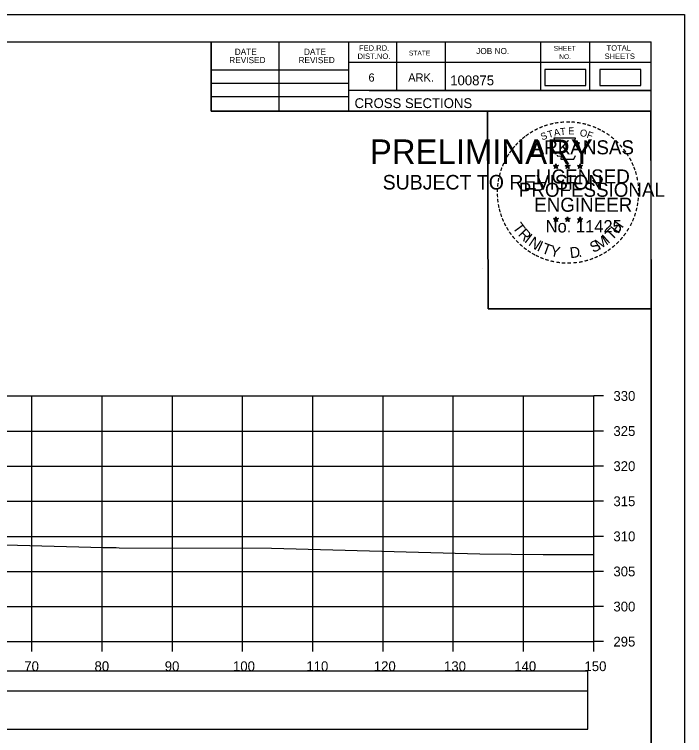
# Model space of a CAD drawing. Extents: x 1368122 to 1710785, y 373130 to 557566.
# Drawn here: x 1370089.7 to 1370185.2, y 375587.6 to 375690.4 of the extents above; entities that cross this region are included whole.
import ezdxf

# ---------------------------------------------------------------- set-up
doc = ezdxf.new("R2010")
doc.units = 0
for name, color, linetype in [('R_Axis', 7, 'Continuous'), ('R_Axis Annot', 7, 'Continuous'), ('R_Border', 7, 'Continuous'), ('R_Border PE', 7, 'Continuous'), ('R_Border Prem', 7, 'Continuous'), ('R_Drive', 7, 'Continuous'), ('R_Exist Surface', 7, 'Continuous'), ('R_Grid', 7, 'Continuous'), ('R_No Plot', 7, 'Continuous')]:
    doc.layers.add(name, color=color, linetype=linetype)

msp = doc.modelspace()

# ---------------------------------------------------------------- linework, layer by layer
for points in [[(1369873.09, 375594.02), (1370171.39, 375594.02), (1370171.39, 375596.84), (1369873.09, 375596.84)], [(1369873.09, 375588.55), (1370171.39, 375588.55), (1370171.39, 375593.96), (1369873.09, 375593.96)]]:
    msp.add_lwpolyline(points, close=True)
at = {"layer": 'R_Axis'}
for p, q in [((1370172.24, 375601.03), (1370172.24, 375636.03)), ((1370173.64, 375636.03), (1370172.24, 375636.03)), ((1370173.64, 375631.03), (1370172.24, 375631.03)), ((1370173.64, 375626.03), (1370172.24, 375626.03)), ((1370173.64, 375621.03), (1370172.24, 375621.03)), ((1370173.64, 375616.03), (1370172.24, 375616.03)), ((1370173.64, 375611.03), (1370172.24, 375611.03)), ((1370173.64, 375606.03), (1370172.24, 375606.03)), ((1369872.24, 375601.03), (1370172.24, 375601.03)), ((1370092.24, 375599.63), (1370092.24, 375601.03)), ((1370102.24, 375599.63), (1370102.24, 375601.03)), ((1370112.24, 375599.63), (1370112.24, 375601.03)), ((1370122.24, 375599.63), (1370122.24, 375601.03)), ((1370132.24, 375599.63), (1370132.24, 375601.03)), ((1370142.24, 375599.63), (1370142.24, 375601.03)), ((1370152.24, 375599.63), (1370152.24, 375601.03)), ((1370162.24, 375599.63), (1370162.24, 375601.03)), ((1370172.24, 375599.63), (1370172.24, 375601.03)), ((1370173.64, 375601.03), (1370172.24, 375601.03))]:
    msp.add_line(p, q, dxfattribs=at)
at = {"layer": 'R_Border'}
for p, q in [((1369864.24, 375686.49), (1370180.42, 375686.49)), ((1370117.78, 375676.61), (1370117.78, 375686.49)), ((1370127.46, 375676.61), (1370127.46, 375686.49)), ((1370137.32, 375686.49), (1370137.32, 375676.61)), ((1370144.16, 375686.49), (1370144.16, 375679.55)), ((1370151.1, 375686.49), (1370151.1, 375679.55)), ((1370164.68, 375686.49), (1370164.68, 375679.55)), ((1370171.62, 375686.49), (1370171.62, 375679.55)), ((1370180.42, 375481.03), (1370180.42, 375686.49)), ((1370180.42, 375683.55), (1370137.32, 375683.55)), ((1370180.42, 375683.57), (1370180.42, 375683.57)), ((1370117.78, 375682.47), (1370137.32, 375682.47)), ((1370117.78, 375680.61), (1370137.32, 375680.61)), ((1370180.42, 375679.55), (1370137.32, 375679.55)), ((1370140.28, 375679.55), (1370180.42, 375679.55)), ((1370117.78, 375678.67), (1370137.32, 375678.67)), ((1370180.42, 375676.61), (1370117.78, 375676.61))]:
    msp.add_line(p, q, dxfattribs=at)
at = {"layer": 'R_Border PE'}
for p, q in [((1370166.51, 375668.86), (1370166.85, 375668.75)), ((1370166.51, 375668.86), (1370166.76, 375668.82)), ((1370166.51, 375668.86), (1370166.74, 375668.74)), ((1370166.64, 375668.45), (1370166.85, 375668.75)), ((1370166.64, 375668.45), (1370166.76, 375668.7)), ((1370166.64, 375668.45), (1370166.85, 375668.67)), ((1370166.85, 375669.12), (1370166.81, 375668.86)), ((1370166.85, 375668.75), (1370166.85, 375669.12)), ((1370166.85, 375669.12), (1370166.9, 375668.87)), ((1370167.2, 375668.86), (1370166.85, 375668.75)), ((1370167.07, 375668.45), (1370166.85, 375668.75)), ((1370167.07, 375668.45), (1370166.85, 375668.67)), ((1370167.2, 375668.86), (1370166.92, 375668.81)), ((1370167.07, 375668.45), (1370166.93, 375668.75)), ((1370167.2, 375668.86), (1370167, 375668.76)), ((1370168.18, 375668.86), (1370168.52, 375668.75)), ((1370168.18, 375668.86), (1370168.43, 375668.82)), ((1370168.18, 375668.86), (1370168.41, 375668.74)), ((1370168.31, 375668.45), (1370168.52, 375668.75)), ((1370168.31, 375668.45), (1370168.43, 375668.7)), ((1370168.31, 375668.45), (1370168.52, 375668.67)), ((1370168.52, 375669.12), (1370168.48, 375668.86)), ((1370168.52, 375668.75), (1370168.52, 375669.12)), ((1370168.52, 375669.12), (1370168.57, 375668.87)), ((1370168.87, 375668.86), (1370168.52, 375668.75)), ((1370168.74, 375668.45), (1370168.52, 375668.75)), ((1370168.74, 375668.45), (1370168.52, 375668.67)), ((1370168.87, 375668.86), (1370168.59, 375668.81)), ((1370168.74, 375668.45), (1370168.6, 375668.75)), ((1370168.87, 375668.86), (1370168.67, 375668.76)), ((1370169.94, 375668.85), (1370170.29, 375668.74)), ((1370169.94, 375668.85), (1370170.19, 375668.81)), ((1370169.94, 375668.85), (1370170.18, 375668.73)), ((1370170.07, 375668.44), (1370170.29, 375668.74)), ((1370170.07, 375668.44), (1370170.2, 375668.69)), ((1370170.07, 375668.44), (1370170.29, 375668.66)), ((1370170.29, 375669.1), (1370170.25, 375668.85)), ((1370170.29, 375668.74), (1370170.29, 375669.1)), ((1370170.29, 375669.1), (1370170.34, 375668.85)), ((1370170.64, 375668.85), (1370170.29, 375668.74)), ((1370170.5, 375668.44), (1370170.29, 375668.74)), ((1370170.5, 375668.44), (1370170.29, 375668.66)), ((1370170.64, 375668.85), (1370170.35, 375668.8)), ((1370170.5, 375668.44), (1370170.36, 375668.73)), ((1370170.64, 375668.85), (1370170.43, 375668.75)), ((1370166.85, 375661.54), (1370166.81, 375661.29)), ((1370166.85, 375661.18), (1370166.85, 375661.54)), ((1370166.85, 375661.54), (1370166.9, 375661.29)), ((1370168.52, 375661.54), (1370168.48, 375661.29)), ((1370168.52, 375661.18), (1370168.52, 375661.54)), ((1370168.52, 375661.54), (1370168.57, 375661.29)), ((1370170.29, 375661.53), (1370170.25, 375661.28)), ((1370170.29, 375661.17), (1370170.29, 375661.53)), ((1370170.29, 375661.53), (1370170.34, 375661.28)), ((1370166.5, 375661.29), (1370166.85, 375661.18)), ((1370166.5, 375661.29), (1370166.75, 375661.24)), ((1370166.5, 375661.29), (1370166.74, 375661.17)), ((1370166.63, 375660.88), (1370166.85, 375661.18)), ((1370166.63, 375660.88), (1370166.76, 375661.13)), ((1370166.63, 375660.88), (1370166.85, 375661.1)), ((1370167.2, 375661.29), (1370166.85, 375661.18)), ((1370167.06, 375660.88), (1370166.85, 375661.18)), ((1370167.06, 375660.88), (1370166.85, 375661.1)), ((1370167.2, 375661.29), (1370166.91, 375661.24)), ((1370167.06, 375660.88), (1370166.93, 375661.17)), ((1370167.2, 375661.29), (1370166.99, 375661.19)), ((1370168.17, 375661.29), (1370168.52, 375661.18)), ((1370168.17, 375661.29), (1370168.42, 375661.24)), ((1370168.17, 375661.29), (1370168.41, 375661.17)), ((1370168.3, 375660.88), (1370168.52, 375661.18)), ((1370168.3, 375660.88), (1370168.43, 375661.13)), ((1370168.3, 375660.88), (1370168.52, 375661.1)), ((1370168.87, 375661.29), (1370168.52, 375661.18)), ((1370168.73, 375660.88), (1370168.52, 375661.18)), ((1370168.73, 375660.88), (1370168.52, 375661.1)), ((1370168.87, 375661.29), (1370168.58, 375661.24)), ((1370168.73, 375660.88), (1370168.6, 375661.17)), ((1370168.87, 375661.29), (1370168.66, 375661.19)), ((1370169.94, 375661.28), (1370170.29, 375661.17)), ((1370169.94, 375661.28), (1370170.19, 375661.23)), ((1370169.94, 375661.28), (1370170.17, 375661.16)), ((1370170.07, 375660.87), (1370170.29, 375661.17)), ((1370170.07, 375660.87), (1370170.2, 375661.12)), ((1370170.07, 375660.87), (1370170.28, 375661.09)), ((1370170.5, 375660.87), (1370170.28, 375661.09)), ((1370170.63, 375661.28), (1370170.29, 375661.17)), ((1370170.5, 375660.87), (1370170.29, 375661.17)), ((1370170.63, 375661.28), (1370170.35, 375661.23)), ((1370170.5, 375660.87), (1370170.36, 375661.16)), ((1370170.63, 375661.28), (1370170.43, 375661.18))]:
    msp.add_line(p, q, dxfattribs=at)
for points in [[(1370166.55, 375672.74), (1370166.82, 375671.91)], [(1370170.06, 375671.82), (1370170.2, 375672.1), (1370169.51, 375672.08), (1370169.66, 375672.74), (1370166.55, 375672.74)], [(1370167.04, 375670.32), (1370167.04, 375670.23), (1370167.6, 375670.21), (1370167.55, 375669.74), (1370169.42, 375669.74), (1370169.62, 375670.27)], [(1370166.85, 375669.12), (1370167.07, 375668.45), (1370166.51, 375668.86), (1370167.2, 375668.86), (1370166.64, 375668.45), (1370166.85, 375669.12)], [(1370168.52, 375669.12), (1370168.74, 375668.45), (1370168.18, 375668.86), (1370168.87, 375668.86), (1370168.31, 375668.45), (1370168.52, 375669.12)], [(1370170.29, 375669.1), (1370170.5, 375668.44), (1370169.94, 375668.85), (1370170.64, 375668.85), (1370170.07, 375668.44), (1370170.29, 375669.1)], [(1370166.85, 375661.54), (1370167.06, 375660.88), (1370166.5, 375661.29), (1370167.2, 375661.29), (1370166.63, 375660.88), (1370166.85, 375661.54)], [(1370168.52, 375661.54), (1370168.73, 375660.88), (1370168.17, 375661.29), (1370168.87, 375661.29), (1370168.3, 375660.88), (1370168.52, 375661.54)], [(1370170.29, 375661.53), (1370170.5, 375660.87), (1370169.94, 375661.28), (1370170.63, 375661.28), (1370170.07, 375660.87), (1370170.29, 375661.53)]]:
    msp.add_lwpolyline(points, dxfattribs=at)
for centre, radius in [((1370166.85, 375668.75), 0.172), ((1370166.85, 375668.75), 0.145), ((1370166.85, 375668.75), 0.116), ((1370166.85, 375668.75), 0.0991), ((1370166.85, 375668.75), 0.0747), ((1370166.85, 375668.75), 0.0495), ((1370166.85, 375668.75), 0.0296), ((1370168.52, 375668.75), 0.172), ((1370168.52, 375668.75), 0.145), ((1370168.52, 375668.75), 0.116), ((1370168.52, 375668.75), 0.0991), ((1370168.52, 375668.75), 0.0747), ((1370168.52, 375668.75), 0.0495), ((1370168.52, 375668.75), 0.0296), ((1370170.29, 375668.74), 0.172), ((1370170.29, 375668.74), 0.145), ((1370170.29, 375668.74), 0.116), ((1370170.29, 375668.74), 0.0991), ((1370170.29, 375668.74), 0.0747), ((1370170.29, 375668.74), 0.0495), ((1370170.29, 375668.74), 0.0296), ((1370166.85, 375661.18), 0.172), ((1370166.85, 375661.18), 0.145), ((1370166.85, 375661.18), 0.116), ((1370166.85, 375661.18), 0.0991), ((1370166.85, 375661.18), 0.0747), ((1370166.85, 375661.18), 0.0495), ((1370166.85, 375661.18), 0.0296), ((1370168.52, 375661.18), 0.172), ((1370168.52, 375661.18), 0.145), ((1370168.52, 375661.18), 0.116), ((1370168.52, 375661.18), 0.0991), ((1370168.52, 375661.18), 0.0747), ((1370168.52, 375661.18), 0.0495), ((1370168.52, 375661.18), 0.0296), ((1370170.29, 375661.17), 0.172), ((1370170.29, 375661.17), 0.145), ((1370170.29, 375661.17), 0.116), ((1370170.29, 375661.17), 0.0991), ((1370170.29, 375661.17), 0.0747), ((1370170.29, 375661.17), 0.0495), ((1370170.29, 375661.17), 0.0296)]:
    msp.add_circle(centre, radius, dxfattribs=at)
at = {"layer": 'R_Drive'}
for points in [[(1370165.29, 375680.24), (1370171.13, 375680.24), (1370171.13, 375682.55), (1370165.29, 375682.55)], [(1370173.1, 375680.24), (1370178.94, 375680.24), (1370178.94, 375682.55), (1370173.1, 375682.55)]]:
    msp.add_lwpolyline(points, close=True, dxfattribs=at)
at = {"layer": 'R_Exist Surface'}
msp.add_lwpolyline([(1370083.17, 375614.97), (1370102.38, 375614.46), (1370104.24, 375614.42), (1370104.68, 375614.41), (1370126.37, 375614.36), (1370156.04, 375613.53), (1370165.03, 375613.45), (1370169.99, 375613.46), (1370172.24, 375613.43)], dxfattribs=at)
at = {"layer": 'R_Grid'}
for p, q in [((1369872.24, 375636.03), (1370172.24, 375636.03)), ((1370092.24, 375601.03), (1370092.24, 375636.03)), ((1370102.24, 375601.03), (1370102.24, 375636.03)), ((1370112.24, 375601.03), (1370112.24, 375636.03)), ((1370122.24, 375601.03), (1370122.24, 375636.03)), ((1370132.24, 375601.03), (1370132.24, 375636.03)), ((1370142.24, 375601.03), (1370142.24, 375636.03)), ((1370152.24, 375601.03), (1370152.24, 375636.03)), ((1370162.24, 375601.03), (1370162.24, 375636.03)), ((1370172.24, 375601.03), (1370172.24, 375636.03)), ((1369872.24, 375631.03), (1370172.24, 375631.03)), ((1369872.24, 375626.03), (1370172.24, 375626.03)), ((1369872.24, 375621.03), (1370172.24, 375621.03)), ((1369872.24, 375616.03), (1370172.24, 375616.03)), ((1369872.24, 375611.03), (1370172.24, 375611.03)), ((1369872.24, 375606.03), (1370172.24, 375606.03)), ((1369872.24, 375601.03), (1370172.24, 375601.03))]:
    msp.add_line(p, q, dxfattribs=at)
at = {"layer": 'R_No Plot'}
for p, q in [((1369851.84, 375690.38), (1370185.17, 375690.38)), ((1370156.45, 375654.15), (1370156.45, 375654.15))]:
    msp.add_line(p, q, dxfattribs=at)
for points in [[(1369851.83, 375690.38), (1370185.17, 375690.38), (1370185.17, 375477.04), (1369851.83, 375477.04)], [(1370098.16, 375686.49), (1370117.78, 375686.49), (1370117.78, 375676.61), (1370133.89, 375676.61), (1370157.09, 375676.61), (1370157.21, 375648.45), (1370180.42, 375648.45), (1370180.42, 375481.03), (1369864.24, 375481.03), (1369864.24, 375686.49)], [(1370157.09, 375676.61), (1370180.3, 375676.61), (1370180.42, 375648.45), (1370157.21, 375648.45)]]:
    msp.add_lwpolyline(points, close=True, dxfattribs=at)

# ---------------------------------------------------------------- texts
at = {"layer": 'R_Axis Annot'}
for s, p in [('330', (1370175.04, 375635.33)), ('325', (1370175.04, 375630.33)), ('320', (1370175.04, 375625.33)), ('315', (1370175.04, 375620.33)), ('310', (1370175.04, 375615.33)), ('305', (1370175.04, 375610.33)), ('300', (1370175.04, 375605.33)), ('295', (1370175.04, 375600.33)), ('70', (1370091.15, 375596.83)), ('80', (1370101.15, 375596.83)), ('90', (1370111.15, 375596.83)), ('100', (1370120.87, 375596.83)), ('110', (1370131.32, 375596.83)), ('120', (1370140.92, 375596.83)), ('130', (1370150.92, 375596.83)), ('140', (1370160.92, 375596.83)), ('150', (1370170.92, 375596.83))]:
    msp.add_text(s, height=1.4, dxfattribs=at).set_placement(p)
at = {"layer": 'R_Border'}
for s, height, p in [('DATE', 0.879, (1370121.12, 375684.62)), ('DATE', 0.879, (1370130.98, 375684.62)), ('FED.RD.', 0.782, (1370138.8, 375685.21)), ('STATE', 0.684, (1370145.92, 375684.53)), ('JOB NO.', 0.879, (1370155.5, 375684.73)), ('SHEET', 0.684, (1370166.54, 375685.21)), ('TOTAL', 0.782, (1370174.06, 375685.21)), ('REVISED', 0.879, (1370120.34, 375683.44)), ('REVISED', 0.879, (1370130.2, 375683.44)), ('DIST.NO.', 0.782, (1370138.6, 375684.03)), ('NO.', 0.684, (1370167.32, 375684.03)), ('SHEETS', 0.782, (1370173.78, 375684.03)), ('6', 1.17, (1370140.16, 375680.81)), ('ARK.', 1.172, (1370145.82, 375680.81)), ('100875', 1.4, (1370151.8, 375680.29)), ('CROSS SECTIONS', 1.4, (1370138.18, 375677.04))]:
    msp.add_text(s, height=height, rotation=360, dxfattribs=at).set_placement(p)
at = {"layer": 'R_Border PE'}
for s, height, rotation, p in [('-', 1.6, 19.1761, (1370165.29, 375673.87)), ('-', 1.6, 13.6301, (1370166.04, 375674.11)), ('-', 1.6, 10.2193, (1370166.72, 375674.27)), ('-', 1.6, 5.8968, (1370167.45, 375674.38)), ('-', 1.6, 0.1862, (1370168.22, 375674.45)), ('-', 1.6, 357.743, (1370168.95, 375674.44)), ('-', 1.6, 352.1617, (1370169.69, 375674.38)), ('-', 1.6, 347.2049, (1370170.41, 375674.27)), ('-', 1.6, 342.3362, (1370171.04, 375674.11)), ('-', 1.6, 34.0636, (1370163.43, 375672.91)), ('-', 1.6, 28.7918, (1370164.03, 375673.28)), ('-', 1.6, 24.3072, (1370164.66, 375673.6)), ('T', 1, 16.4036, (1370165.82, 375672.75)), ('A', 1, 11.2132, (1370166.64, 375673)), ('T', 1, 6.0228, (1370167.49, 375673.17)), ('E', 1, 0.8323, (1370168.6, 375673.28)), ('O', 1, 350.4515, (1370170.2, 375673.07)), ('F', 1, 340.0707, (1370171.15, 375672.84)), ('-', 1.6, 337.8551, (1370171.78, 375673.89)), ('-', 1.6, 334.1211, (1370172.41, 375673.62)), ('-', 1.6, 329.6409, (1370172.99, 375673.34)), ('-', 1.6, 42.9622, (1370161.94, 375671.72)), ('-', 1.6, 38.9507, (1370162.38, 375672.14)), ('-', 1.6, 36.2317, (1370162.85, 375672.52)), ('S', 1, 21.594, (1370164.9, 375672.42)), ('-', 1.6, 325.8627, (1370173.63, 375672.98)), ('-', 1.6, 320.5297, (1370174.24, 375672.55)), ('-', 1.6, 50.6142, (1370161.09, 375670.76)), ('-', 1.6, 48.423, (1370161.5, 375671.24)), ('ARKANSAS', 2, 360, (1370163.4, 375670.45)), ('-', 1.6, 315.5786, (1370174.84, 375672.06)), ('-', 1.6, 309.8797, (1370175.41, 375671.51)), ('-', 1.6, 54.2325, (1370160.68, 375670.19)), ('-', 1.6, 306.6522, (1370175.94, 375670.91)), ('-', 1.4, 303.6753, (1370176.42, 375670.34)), ('-', 1.6, 62.8713, (1370160.04, 375669.05)), ('-', 1.6, 58.0706, (1370160.35, 375669.66)), ('-', 1.6, 299.6684, (1370176.74, 375669.74)), ('-', 1.6, 72.3945, (1370159.56, 375667.81)), ('-', 1.6, 67.7743, (1370159.78, 375668.44)), ('DWB', 0.01, 360, (1370166.84, 375668.75)), ('DWB', 0.01, 360, (1370168.51, 375668.75)), ('DWB', 0.01, 360, (1370170.28, 375668.74)), ('-', 1.6, 294.6628, (1370177.06, 375669.12)), ('-', 1.6, 290.5728, (1370177.32, 375668.55)), ('-', 1.6, 75.461, (1370159.37, 375667.09)), ('LICENSED', 2, 360, (1370164, 375666.3)), ('-', 1.6, 285.1233, (1370177.56, 375667.97)), ('-', 1.6, 81.2013, (1370159.23, 375666.38)), ('-', 1.6, 280.5493, (1370177.76, 375667.22)), ('-', 1.6, 89.0622, (1370159.13, 375664.99)), ('-', 1.6, 85.1863, (1370159.16, 375665.69)), ('PROFESSIONAL', 2, 360, (1370161.57, 375664.4)), ('-', 1.6, 276.5962, (1370177.92, 375666.46)), ('-', 1.6, 274.3301, (1370177.98, 375665.73)), ('-', 1.6, 94.1959, (1370159.17, 375664.26)), ('-', 1.6, 269.9407, (1370178.01, 375665.1)), ('-', 1.6, 98.9479, (1370159.24, 375663.6)), ('ENGINEER', 2, 360, (1370163.76, 375662.27)), ('-', 1.6, 260.9953, (1370177.92, 375663.78)), ('-', 1.6, 263.5172, (1370177.99, 375664.44)), ('-', 1.6, 101.7149, (1370159.38, 375662.86)), ('-', 1.6, 105.4578, (1370159.54, 375662.27)), ('-', 1.6, 255.7626, (1370177.81, 375663.1)), ('-', 1.6, 109.0874, (1370159.75, 375661.64)), ('-', 1.6, 114.0643, (1370160.01, 375661.04)), ('-', 1.6, 247.8887, (1370177.41, 375661.71)), ('-', 1.6, 252.8681, (1370177.63, 375662.38)), ('-', 1.6, 115.7289, (1370160.31, 375660.42)), ('T', 1.54, 306.0406, (1370160.61, 375660.02)), ('No. 11425', 1.757, 360, (1370165.39, 375659.32)), ('DWB', 0.01, 360, (1370166.84, 375661.17)), ('DWB', 0.01, 360, (1370168.51, 375661.17)), ('DWB', 0.01, 360, (1370170.27, 375661.16)), ('H', 1.54, 54.6088, (1370175.73, 375659.05)), ('-', 1.6, 244.6197, (1370177.15, 375661.08)), ('-', 1.6, 120.4471, (1370160.67, 375659.84)), ('-', 1.6, 125.8934, (1370161.07, 375659.28)), ('R', 1.54, 314.005, (1370161.37, 375658.97)), ('T', 1.54, 46.6444, (1370174.84, 375658.11)), ('-', 1.6, 239.0712, (1370176.75, 375660.33)), ('-', 1.6, 130.7181, (1370161.53, 375658.73)), ('I', 1.54, 321.9694, (1370162.27, 375658.04)), ('N', 1.54, 326.5002, (1370162.84, 375657.56)), ('M', 1.54, 32.6563, (1370172.99, 375656.78)), ('I', 1.54, 42.1136, (1370174.28, 375657.63)), ('-', 1.6, 231.2538, (1370175.92, 375659.11)), ('-', 1.6, 233.8452, (1370176.35, 375659.68)), ('-', 1.6, 134.2238, (1370162.05, 375658.18)), ('-', 1.6, 138.9338, (1370162.58, 375657.72)), ('I', 1.54, 335.3603, (1370164.05, 375656.78)), ('T', 1.54, 339.8912, (1370164.71, 375656.45)), ('Y', 1.54, 347.8556, (1370165.93, 375656.01)), ('D', 1.54, 6.3969, (1370168.91, 375655.65)), ('S', 1.54, 26.9312, (1370172.16, 375656.38)), ('-', 1.6, 221.0851, (1370174.92, 375658.04)), ('-', 1.6, 225.7653, (1370175.44, 375658.55)), ('-', 1.6, 144.6463, (1370163.13, 375657.31)), ('-', 1.6, 148.0898, (1370163.69, 375656.94)), ('-', 1.6, 151.5704, (1370164.27, 375656.61)), ('-', 1.6, 207.3568, (1370173.28, 375656.83)), ('-', 1.6, 212.2491, (1370173.84, 375657.18)), ('-', 1.6, 215.7363, (1370174.37, 375657.57)), ('-', 1.6, 154.6002, (1370164.79, 375656.37)), ('-', 1.6, 158.5612, (1370165.42, 375656.11)), ('-', 1.6, 162.7983, (1370166.1, 375655.9)), ('-', 1.6, 167.5555, (1370166.82, 375655.74)), ('-', 1.6, 191.2858, (1370170.63, 375655.8)), ('.', 1.54, 13.7642, (1370170.1, 375655.78)), ('-', 1.6, 195.4743, (1370171.36, 375656)), ('-', 1.6, 200.7184, (1370172.03, 375656.24)), ('-', 1.6, 204.2516, (1370172.65, 375656.51)), ('-', 1.6, 173.1155, (1370167.59, 375655.63)), ('-', 1.6, 176.5183, (1370168.34, 375655.57)), ('-', 1.6, 181.5918, (1370169.08, 375655.59)), ('-', 1.6, 185.8167, (1370169.89, 375655.67))]:
    msp.add_text(s, height=height, rotation=rotation, dxfattribs=at).set_placement(p)
at = {"layer": 'R_Border Prem'}
for s, height, p in [('PRELIMINARY', 3.5, (1370140.37, 375669.07)), ('DWB', 0.01, (1370141.12, 375670.92)), ('SUBJECT TO REVISION', 2.0751, (1370142.18, 375665.44))]:
    msp.add_text(s, height=height, rotation=360, dxfattribs=at).set_placement(p)

doc.saveas('drawing.dxf')
